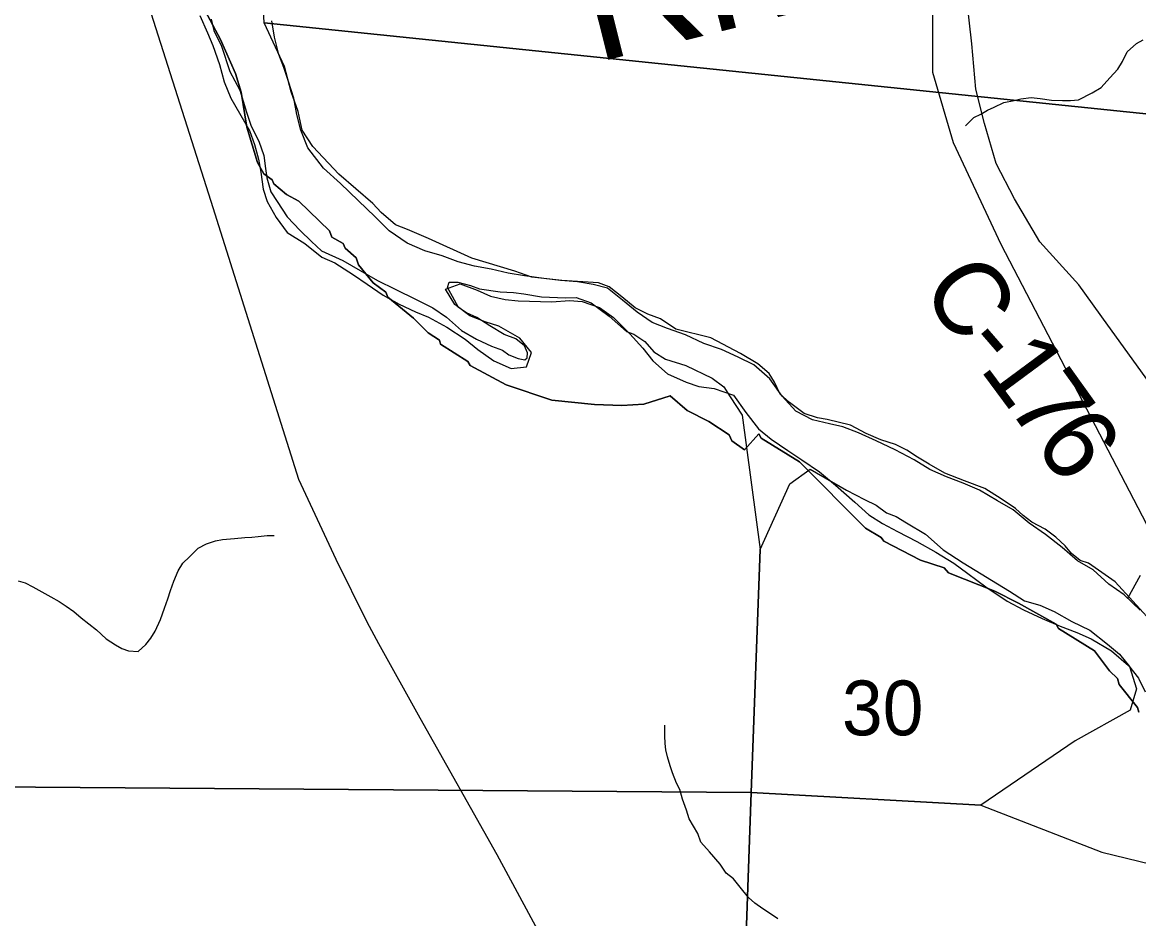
# Model space of a CAD drawing. Extents: x 0 to 34, y 0 to 22.
# Drawn here: x 3.401 to 4.254, y 18.706 to 19.391 of the extents above; entities that cross this region are included whole.
import ezdxf

# ---------------------------------------------------------------- set-up
doc = ezdxf.new("R2010")
doc.units = 0
for name, color, linetype in [('GM_X_County_Road', 7, 'Continuous'), ('GM_X_County_Road_Text', 7, 'Continuous'), ('GM_X_Major_River', 7, 'Continuous'), ('GM_X_Major_River_Text', 7, 'Continuous'), ('GM_X_Minor_River', 7, 'Continuous'), ('GM_X_Rail_Line', 7, 'Continuous'), ('GM_X_Section', 7, 'Continuous'), ('GM_X_Section_Text', 7, 'Continuous'), ('GM_X_State_Route', 7, 'Continuous')]:
    doc.layers.add(name, color=color, linetype=linetype)

msp = doc.modelspace()

# ---------------------------------------------------------------- linework, layer by layer
at = {"layer": 'GM_X_County_Road'}
msp.add_lwpolyline([(4.30895, 19.04802), (4.27266, 19.10152), (4.23095, 19.15944), (4.20883, 19.19016), (4.17882, 19.22302), (4.15943, 19.25592), (4.14552, 19.28296), (4.13667, 19.31362), (4.12994, 19.33966), (4.1269, 19.37432), (4.12279, 19.41092)], dxfattribs=at)
at = {"layer": 'GM_X_Major_River'}
for points in [[(3.53721, 19.396), (3.54288, 19.38291), (3.54714, 19.37327), (3.552, 19.35868), (3.55576, 19.34527), (3.56069, 19.33295), (3.57511, 19.30819), (3.57895, 19.29743), (3.58202, 19.28631), (3.58361, 19.27638), (3.58549, 19.26341), (3.5886, 19.25381), (3.59545, 19.24182), (3.60382, 19.23016), (3.61723, 19.22176), (3.6302, 19.21148), (3.64031, 19.20698), (3.65445, 19.1978), (3.66486, 19.19064), (3.67714, 19.18228), (3.68945, 19.17544), (3.70181, 19.16973), (3.71193, 19.16562), (3.72574, 19.15797), (3.73989, 19.14879)], [(3.68171, 19.23154), (3.67103, 19.24213), (3.65813, 19.25469), (3.64448, 19.26765), (3.63156, 19.27945), (3.61951, 19.29503), (3.61424, 19.30849), (3.61119, 19.32037), (3.60892, 19.33298), (3.60476, 19.34564), (3.6013, 19.35639), (3.59743, 19.36639), (3.59404, 19.37942), (3.59215, 19.39202)], [(4.25558, 18.94167), (4.24342, 18.95344), (4.23152, 18.96141), (4.21971, 18.97242), (4.20777, 18.97924), (4.19594, 18.98949), (4.18333, 18.99938), (4.17069, 19.00813), (4.15848, 19.01839), (4.14654, 19.02522), (4.13274, 19.03325), (4.12038, 19.03857), (4.10762, 19.04353), (4.09489, 19.04924), (4.08296, 19.05645), (4.06839, 19.06412), (4.05379, 19.07103), (4.04031, 19.07715), (4.0283, 19.0817), (4.01812, 19.08392), (4.0053, 19.08698), (3.9926, 19.09383), (3.98195, 19.10518), (3.97249, 19.11839), (3.96029, 19.12903), (3.94832, 19.1351), (3.93559, 19.14082), (3.92206, 19.14542), (3.90821, 19.15193), (3.89432, 19.15692), (3.88269, 19.16146), (3.87117, 19.16942), (3.86006, 19.1785), (3.84857, 19.1876), (3.83765, 19.1906), (3.82555, 19.19249), (3.81268, 19.19365), (3.79982, 19.19519), (3.78507, 19.19717), (3.7726, 19.19908), (3.75978, 19.20213), (3.74694, 19.20443), (3.73451, 19.20786), (3.72213, 19.21242), (3.70895, 19.21625), (3.69546, 19.22199), (3.68171, 19.23154)], [(3.73989, 19.14879), (3.74952, 19.14089), (3.76178, 19.13215), (3.77489, 19.12643), (3.7867, 19.12758), (3.79045, 19.13848), (3.78168, 19.14939), (3.76564, 19.15863), (3.75511, 19.162), (3.74348, 19.16654), (3.73198, 19.17526), (3.72475, 19.18688), (3.73589, 19.1911), (3.74903, 19.18613), (3.75914, 19.18163), (3.77045, 19.179), (3.78029, 19.17794), (3.80609, 19.17714), (3.81942, 19.17824), (3.82927, 19.17756), (3.84241, 19.17297), (3.85319, 19.16541), (3.86571, 19.15287), (3.87562, 19.14192), (3.8833, 19.13218), (3.89438, 19.12234), (3.90861, 19.11581), (3.91838, 19.11247), (3.9301, 19.11097), (3.94476, 19.10596), (3.95422, 19.09274), (3.96408, 19.08028), (3.97371, 19.07238), (3.98635, 19.06363), (3.99713, 19.05645), (4.01052, 19.0473), (4.02273, 19.03704), (4.03752, 19.02404), (4.04824, 19.01459), (4.05866, 19.00781), (4.07024, 19.00174), (4.08481, 18.99407), (4.09937, 18.98602), (4.11316, 18.97762), (4.12393, 18.96968), (4.13766, 18.95938), (4.15403, 18.94861), (4.16635, 18.94177), (4.18057, 18.93525), (4.19445, 18.9295), (4.2072, 18.92454), (4.21806, 18.91965), (4.23372, 18.91042), (4.24667, 18.89938), (4.25434, 18.88965), (4.25933, 18.87923)]]:
    msp.add_lwpolyline(points, dxfattribs=at)
at = {"layer": 'GM_X_Minor_River'}
for points in [[(4.12224, 19.31189), (4.12853, 19.31813), (4.13393, 19.32061), (4.13898, 19.32385), (4.14399, 19.32596), (4.15133, 19.32951), (4.15935, 19.33113), (4.16434, 19.33248), (4.17234, 19.33334), (4.17915, 19.33272), (4.18783, 19.33128), (4.19618, 19.331), (4.20226, 19.33117), (4.20835, 19.33172), (4.21878, 19.33706), (4.22576, 19.341), (4.23246, 19.34836), (4.23839, 19.355), (4.24201, 19.36096), (4.24569, 19.36843), (4.25274, 19.37465), (4.25777, 19.37751)], [(3.39835, 18.96411), (3.40361, 18.96241), (3.40958, 18.95954), (3.42336, 18.95185), (3.42969, 18.94821), (3.43488, 18.94461), (3.44082, 18.9406), (3.44635, 18.93585), (3.45226, 18.93108), (3.45818, 18.9267), (3.46553, 18.9196), (3.47259, 18.91518), (3.47743, 18.91235), (3.48269, 18.91064), (3.48988, 18.91002), (3.49576, 18.91551), (3.49973, 18.92032), (3.50294, 18.92553), (3.50705, 18.93451), (3.51001, 18.94314), (3.51253, 18.95028), (3.51465, 18.95667), (3.51717, 18.9638), (3.52048, 18.97167), (3.52411, 18.97762), (3.52921, 18.98239), (3.53589, 18.98899), (3.54208, 18.9922), (3.54899, 18.99462), (3.55434, 18.99558), (3.56348, 18.9964), (3.57149, 18.99726), (3.57681, 18.99746), (3.58176, 18.99805), (3.58861, 18.99857), (3.59394, 18.99877)], [(4.24609, 18.95086), (4.25577, 18.96828)], [(3.96122, 18.71775), (3.95644, 18.7221), (3.94987, 18.72992), (3.94478, 18.73618), (3.93923, 18.74055), (3.93454, 18.74755), (3.92651, 18.75695), (3.91993, 18.7644), (3.9175, 18.77095), (3.91106, 18.78219), (3.909, 18.78872), (3.90588, 18.79719), (3.90385, 18.80448), (3.90137, 18.80951), (3.89822, 18.81722), (3.89651, 18.8226), (3.89447, 18.82951), (3.89314, 18.83488), (3.89255, 18.83984), (3.89237, 18.84554), (3.89226, 18.85353), (3.89227, 18.8538)], [(3.97865, 18.70574), (3.97383, 18.70895), (3.96715, 18.71336), (3.96122, 18.71775)]]:
    msp.add_lwpolyline(points, dxfattribs=at)
at = {"layer": 'GM_X_Rail_Line'}
msp.add_lwpolyline([(5.16152, 17.57226), (5.08803, 17.59895), (5.0342, 17.60528), (4.88696, 17.61951), (4.82997, 17.63534), (4.77242, 17.67316), (4.74038, 17.72477), (4.72366, 17.77586), (4.71104, 17.81738), (4.61799, 18.21165), (4.59934, 18.26519), (4.58837, 18.30891), (4.57053, 18.37994), (4.54663, 18.43849), (4.38833, 18.76166), (4.14931, 19.22108), (4.1129, 19.29871), (4.09707, 19.35258), (4.09708, 19.41754)], dxfattribs=at)
at = {"layer": 'GM_X_Section'}
for points in [[(4.67188, 20.19287), (4.58089, 19.28794), (3.58626, 19.39052), (3.58498, 19.41556)], [(3.5458, 19.3934), (3.54785, 19.38463), (3.55363, 19.37275), (3.55997, 19.35328), (3.56759, 19.33908), (3.57286, 19.32228), (3.57639, 19.31158), (3.58217, 19.30007), (3.58607, 19.28899), (3.58734, 19.27912), (3.5883, 19.2719), (3.59145, 19.26121), (3.5962, 19.2539), (3.60388, 19.24234), (3.61385, 19.23187), (3.62236, 19.22333), (3.63014, 19.21632), (3.64625, 19.20873), (3.67278, 19.19369), (3.68626, 19.18693), (3.70236, 19.17896), (3.71508, 19.17259), (3.72552, 19.16552), (3.73701, 19.15539), (3.7486, 19.14867), (3.75983, 19.14347), (3.76847, 19.14022), (3.77331, 19.1367), (3.78044, 19.13387), (3.78534, 19.13299), (3.78727, 19.13447), (3.78737, 19.13825), (3.78522, 19.14361), (3.77854, 19.14907), (3.76952, 19.15233), (3.7587, 19.15903), (3.74862, 19.16533), (3.74075, 19.16893), (3.73478, 19.17287), (3.73007, 19.18132), (3.72645, 19.18822), (3.72768, 19.19236), (3.73412, 19.1922), (3.74391, 19.18969), (3.75067, 19.18725), (3.76653, 19.18498), (3.77674, 19.18435), (3.78467, 19.1834), (3.79826, 19.18118), (3.81642, 19.18035), (3.82476, 19.18053), (3.83603, 19.17647), (3.8498, 19.16629), (3.86315, 19.15459), (3.86878, 19.15256), (3.87698, 19.14706), (3.88398, 19.13894), (3.89294, 19.13342), (3.90835, 19.12849), (3.92858, 19.11891), (3.93751, 19.11226), (3.94225, 19.10456), (3.95138, 19.0907), (3.96518, 18.98808), (3.9584, 18.80223), (2.96714, 18.80963)], [(4.26869, 18.92805), (4.24987, 18.94858), (4.23659, 18.9633), (4.2161, 18.97744), (4.2097, 18.97949), (4.20302, 18.98496), (4.19824, 18.99076), (4.1912, 18.99736), (4.18301, 19.00362), (4.17291, 19.00879), (4.16621, 19.01389), (4.16029, 19.01933), (4.14948, 19.02679), (4.13679, 19.03468), (4.1214, 19.04035), (4.10639, 19.0464), (4.09443, 19.05313), (4.08547, 19.05866), (4.07726, 19.06378), (4.06865, 19.06815), (4.05738, 19.07184), (4.04613, 19.07666), (4.03416, 19.08301), (4.01646, 19.08723), (4.00891, 19.08854), (3.99876, 19.09182), (3.98761, 19.10043), (3.98056, 19.10666), (3.97624, 19.11586), (3.97223, 19.12239), (3.96332, 19.12981), (3.95025, 19.13771), (3.92743, 19.14963), (3.9007, 19.15634), (3.88914, 19.16419), (3.87938, 19.16784), (3.86965, 19.17262), (3.85963, 19.1812), (3.84996, 19.18864), (3.8417, 19.19186), (3.81371, 19.19368), (3.79066, 19.19614), (3.77789, 19.20061), (3.7448, 19.21051), (3.71182, 19.2257), (3.6957, 19.23254), (3.68669, 19.23617), (3.67556, 19.24553), (3.66929, 19.2525), (3.64331, 19.27472), (3.62337, 19.29604), (3.61533, 19.30836), (3.61228, 19.32284), (3.60695, 19.33774), (3.60174, 19.35719), (3.58626, 19.39052), (4.58089, 19.28794)], [(4.25494, 17.7998), (4.24193, 17.79444), (4.22001, 17.78133), (3.92299, 17.79649), (3.9584, 18.80223), (4.13395, 18.79266), (4.22627, 18.75671), (4.30272, 18.73818)]]:
    msp.add_lwpolyline(points, dxfattribs=at)
for points in [[(3.9584, 18.80223), (3.96518, 18.98808), (3.98799, 19.03829), (4.00341, 19.04928), (4.03107, 19.03345), (4.04491, 19.0263), (4.05389, 19.02192), (4.06171, 19.01604), (4.06922, 19.01321), (4.07706, 19.00847), (4.09162, 18.99978), (4.10496, 18.98772), (4.12026, 18.97787), (4.15573, 18.95618), (4.16728, 18.9487), (4.17895, 18.94538), (4.18982, 18.94057), (4.20327, 18.93305), (4.21713, 18.92627), (4.23051, 18.91572), (4.23979, 18.90791), (4.24752, 18.89863), (4.25279, 18.88146), (4.24785, 18.86529), (4.20598, 18.84168), (4.13395, 18.79266)], [(2.96714, 18.80963), (3.9584, 18.80223), (3.92299, 17.79649), (2.93343, 17.81142)]]:
    msp.add_lwpolyline(points, close=True, dxfattribs=at)
at = {"layer": 'GM_X_State_Route'}
for points in [[(3.8721, 18.55519), (3.85915, 18.57872), (3.76419, 18.75474), (3.70539, 18.85908), (3.67386, 18.91588), (3.66486, 18.93239), (3.64134, 18.98043), (3.61281, 19.04149), (3.54577, 19.2539), (3.47803, 19.46696), (3.44542, 19.57897), (3.44165, 19.62804), (3.44885, 19.67609), (3.46345, 19.71601), (3.49295, 19.76127), (3.49665, 19.7654), (3.53657, 19.81001), (3.63324, 19.90612)], [(3.52182, 19.43619), (3.55283, 19.37775), (3.56442, 19.35166), (3.56867, 19.33751), (3.57303, 19.31081), (3.58118, 19.28365), (3.58594, 19.27518), (3.59229, 19.27048), (3.59374, 19.26742), (3.60344, 19.25923), (3.61281, 19.25409), (3.63624, 19.23154), (3.63803, 19.22657), (3.64665, 19.22182), (3.6481, 19.21836), (3.65667, 19.21096), (3.65845, 19.20561), (3.66954, 19.19169), (3.67926, 19.18464), (3.68069, 19.18081), (3.70046, 19.1648), (3.71161, 19.15354), (3.72022, 19.14804), (3.72091, 19.14499), (3.74188, 19.13161), (3.74371, 19.12854), (3.7711, 19.11389), (3.80614, 19.10212), (3.8387, 19.09877), (3.85955, 19.09795), (3.87627, 19.09911), (3.89652, 19.10552), (3.90957, 19.09423), (3.92608, 19.08589), (3.94142, 19.07569), (3.94361, 19.07107), (3.95332, 19.06403), (3.96419, 19.07626), (3.96602, 19.07317), (3.99523, 19.05507), (4.04576, 19.00421), (4.05775, 18.99711), (4.0596, 18.99442), (4.08774, 18.97976), (4.10583, 18.97405), (4.10917, 18.97018), (4.14454, 18.95613), (4.16256, 18.947), (4.19143, 18.93081), (4.19327, 18.92772), (4.22059, 18.91043), (4.23204, 18.89536), (4.23836, 18.88952), (4.23941, 18.88494), (4.25345, 18.86716), (4.25451, 18.86372)], [(4.25451, 18.86372), (4.25345, 18.86716), (4.23941, 18.88494), (4.23836, 18.88952), (4.23204, 18.89536), (4.22059, 18.91043), (4.19327, 18.92772), (4.19143, 18.93081), (4.16256, 18.947), (4.14454, 18.95613), (4.10917, 18.97018), (4.10583, 18.97405), (4.08774, 18.97976), (4.0596, 18.99442), (4.05775, 18.99711), (4.04576, 19.00421), (3.99523, 19.05507), (3.96602, 19.07317), (3.96419, 19.07626), (3.95332, 19.06403), (3.94361, 19.07107), (3.94142, 19.07569), (3.92608, 19.08589), (3.90957, 19.09423), (3.89652, 19.10552), (3.87627, 19.09911), (3.85955, 19.09795), (3.8387, 19.09877), (3.80614, 19.10212), (3.7711, 19.11389), (3.74371, 19.12854), (3.74188, 19.13161), (3.72091, 19.14499), (3.72022, 19.14804), (3.71161, 19.15354), (3.70046, 19.1648), (3.68069, 19.18081), (3.67926, 19.18464), (3.66954, 19.19169), (3.65845, 19.20561), (3.65667, 19.21096), (3.6481, 19.21836), (3.64665, 19.22182), (3.63803, 19.22657), (3.63624, 19.23154), (3.61281, 19.25409), (3.60344, 19.25923), (3.59374, 19.26742), (3.59229, 19.27048), (3.58594, 19.27518), (3.58118, 19.28365), (3.57303, 19.31081), (3.56867, 19.33751), (3.56442, 19.35166), (3.55283, 19.37775), (3.52182, 19.43619)]]:
    msp.add_lwpolyline(points, dxfattribs=at)

# ---------------------------------------------------------------- texts
at = {"layer": 'GM_X_County_Road_Text'}
for s, rotation, p in [('C', 303.93824, (4.08713, 19.18771)), ('-', 310.89753, (4.11776, 19.14302)), ('1', 306.51082, (4.13231, 19.12628)), ('7', 305.62298, (4.153, 19.09834)), ('6', 305.34183, (4.17334, 19.06994))]:
    msp.add_text(s, height=0.05682, rotation=rotation, dxfattribs=at).set_placement(p)
at = {"layer": 'GM_X_Major_River_Text'}
msp.add_text('River', height=0.094698, rotation=14.13624, dxfattribs=at).set_placement((3.83907, 19.35967))
at = {"layer": 'GM_X_Section_Text'}
msp.add_text('30', height=0.041856, rotation=0.00001, dxfattribs=at).set_placement((4.02772, 18.84599))

doc.saveas('drawing.dxf')
